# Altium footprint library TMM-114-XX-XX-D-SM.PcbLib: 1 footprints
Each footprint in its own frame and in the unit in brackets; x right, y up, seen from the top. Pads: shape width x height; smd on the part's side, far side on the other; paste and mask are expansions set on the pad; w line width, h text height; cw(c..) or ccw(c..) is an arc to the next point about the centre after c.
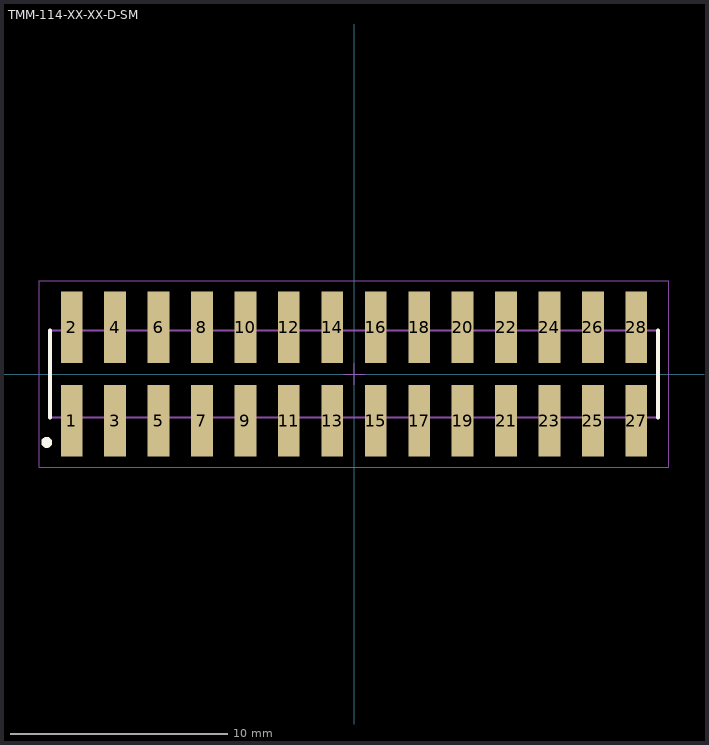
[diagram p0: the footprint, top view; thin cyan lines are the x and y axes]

## TMM-114-XX-XX-D-SM [mm] "2.00mm pitch, 28 pin, terminal strip; double row, SMT"
height 2.77
pads (28):
  rect 1x3.3 smd mask+0: 1(-13,-2.15) 2(-13,2.15) 3(-11,-2.15) 4(-11,2.15) 5(-9,-2.15) 6(-9,2.15) 7(-7,-2.15) 8(-7,2.15) 9(-5,-2.15) 10(-5,2.15) 11(-3,-2.15) 12(-3,2.15) 13(-1,-2.15) 14(-1,2.15) 15(1,-2.15) 16(1,2.15) 17(3,-2.15) 18(3,2.15) 19(5,-2.15) 20(5,2.15) 21(7,-2.15) 22(7,2.15) 23(9,-2.15) 24(9,2.15) 25(11,-2.15) 26(11,2.15) 27(13,-2.15) 28(13,2.15)
Top Overlay:
  circle w0.25: c-14.15,-3.15 r0.125
  lines w0.2: -14,-2 -14,2 ; 14,-2 14,2
Mechanical 12:
  lines w0.001: -14,-2 -14,2 14,2 14,-2 -14,-2
Mechanical 13:
  lines w0.1: -14,-2 -14,2 14,2 14,-2 -14,-2
  text ".Designator" at 0,-0.127 h1.52
Mechanical 15:
  lines w0.05: -0.5,0 0.5,0 ; 0,-0.5 0,0.5 ; -14.5,-4.3 -14.5,4.3 14.5,4.3 14.5,-4.3 -14.5,-4.3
